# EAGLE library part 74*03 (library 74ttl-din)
Quad 2-input NAND gate, open collector output
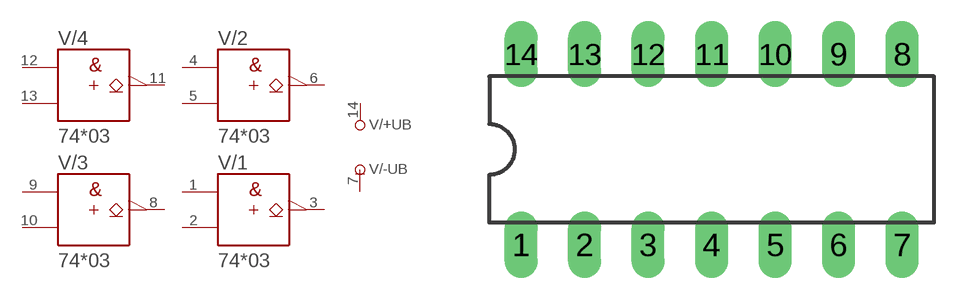
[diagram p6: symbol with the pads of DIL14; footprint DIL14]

Designator prefix V; gates /+UB=+UB /-UB=-UB /1=03 /2=03 /3=03 /4=03

## 7403N  [DIL14]
1  /1:A  in
2  /1:B  in
3  /1:Y  oc
4  /2:A  in
5  /2:B  in
6  /2:Y  oc
7  /-UB:-UB  pwr
8  /3:Y  oc
9  /3:A  in
10  /3:B  in
11  /4:Y  oc
12  /4:A  in
13  /4:B  in
14  /+UB:+UB  pwr

## Footprint DIL14 (pad centres in mm)
Dual In Line Package
drill 0.813 long: 1 -7.62,-3.81; 2 -5.08,-3.81; 3 -2.54,-3.81; 4 0,-3.81; 5 2.54,-3.81; 6 5.08,-3.81; 7 7.62,-3.81; 8 7.62,3.81; 9 5.08,3.81; 10 2.54,3.81; 11 0,3.81; 12 -2.54,3.81; 13 -5.08,3.81; 14 -7.62,3.81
